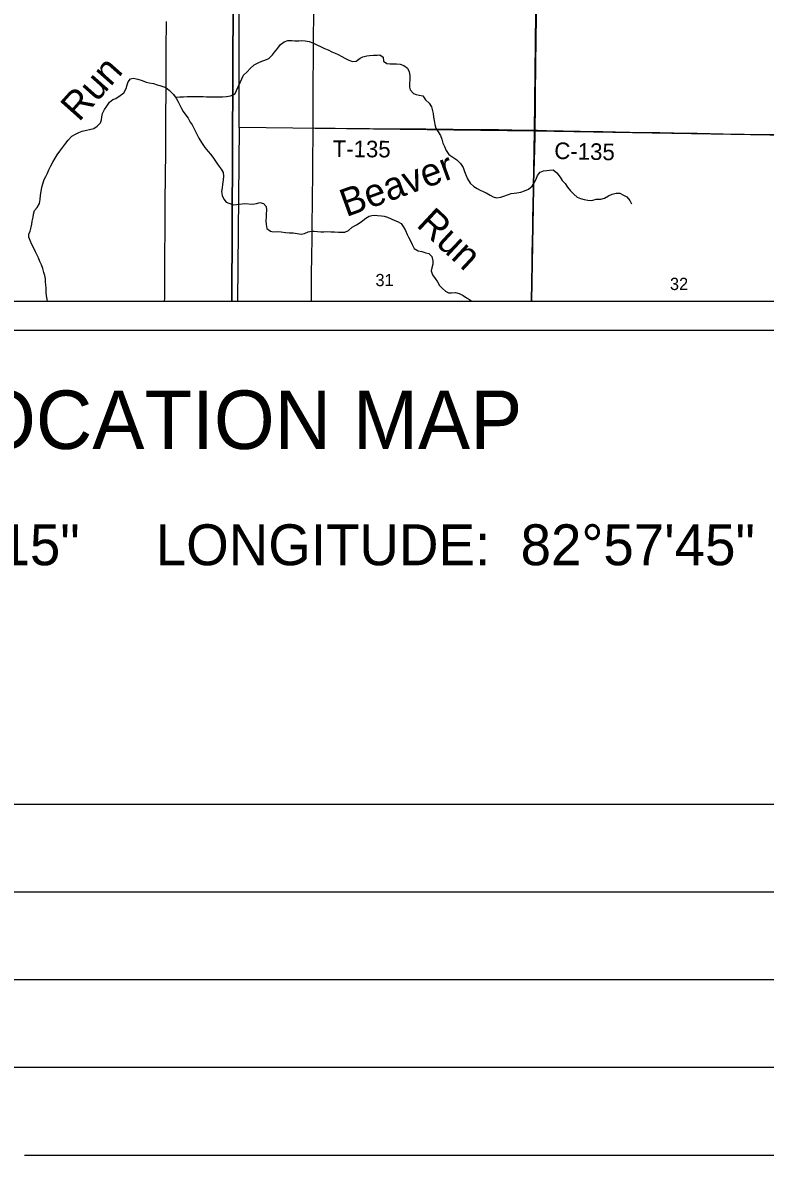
# Model space of a CAD drawing. Extents: x 0 to 45.9, y 0 to 22.
# Drawn here: x 4.739 to 7.28, y 11.177 to 15.053 of the extents above; entities that cross this region are included whole.
import ezdxf

# ---------------------------------------------------------------- set-up
doc = ezdxf.new("R2010")
doc.units = 0
for name, color, linetype in [('Default', 7, 'Continuous'), ('GM_X_County_Road', 7, 'Continuous'), ('GM_X_County_Road_Text', 7, 'Continuous'), ('GM_X_Minor_River', 7, 'Continuous'), ('GM_X_Minor_River_Text', 7, 'Continuous'), ('GM_X_Section', 7, 'Continuous'), ('GM_X_Section_Text', 7, 'Continuous'), ('GM_X_State_Route', 7, 'Continuous'), ('GM_X_Township_Road', 7, 'Continuous'), ('GM_X_Township_Road_Text', 7, 'Continuous'), ('SH_Border', 7, 'Continuous'), ('SH_Cut_Line', 7, 'Continuous'), ('SH_Text', 7, 'Continuous')]:
    doc.layers.add(name, color=color, linetype=linetype)

msp = doc.modelspace()

# ---------------------------------------------------------------- linework, layer by layer
at = {"layer": 'Default'}
msp.add_lwpolyline([(5.4606, 15.6588), (5.4538, 14.1), (8.9, 14.1), (8.9, 19.7611)], dxfattribs=at)
for points in [[(2.1, 19.7114), (2.1, 14.1), (5.4538, 14.1), (5.4606, 15.6588), (5.4651, 16.7018), (5.4694, 17.7061), (5.4802, 18.3214), (5.4737, 18.7216), (5.4752, 19.0482), (5.4759, 19.2109), (5.4773, 19.7108), (5.0826, 19.712), (3.7367, 19.7072), (2.15, 19.7113)], [(5.4738, 14.1), (6.4798, 14.1), (6.4893, 14.6816), (5.4789, 14.694)], [(6.4798, 14.1), (7.4874, 14.1), (7.4967, 14.6639), (6.4893, 14.6816)]]:
    msp.add_lwpolyline(points, close=True, dxfattribs=at)
at = {"layer": 'GM_X_County_Road'}
for points in [[(6.4922, 14.6848), (6.4925, 14.7031), (6.4931, 14.7497), (6.4935, 14.7963), (6.4943, 14.9175), (6.495, 14.9858), (6.496, 15.079), (6.4964, 15.1318), (6.497, 15.166), (6.4974, 15.1877), (6.4974, 15.225), (6.4976, 15.2871), (6.4982, 15.343), (6.4985, 15.3834), (6.4988, 15.4145), (6.499, 15.4642), (6.4995, 15.5077), (6.5001, 15.5667), (6.5003, 15.6009), (6.5006, 15.6413), (6.5009, 15.6926)], [(6.4795, 14.1), (6.4798, 14.11), (6.4802, 14.1348), (6.4804, 14.1721), (6.4812, 14.2156), (6.4819, 14.2653), (6.4835, 14.3429), (6.4842, 14.3833), (6.4852, 14.4268), (6.4865, 14.4733), (6.4877, 14.5137), (6.4896, 14.5789), (6.4919, 14.6628), (6.4922, 14.6848)], [(6.4922, 14.6848), (6.4995, 14.6846), (6.5306, 14.6838), (6.6454, 14.6815), (6.723, 14.6799), (6.7664, 14.6789), (6.8161, 14.678), (6.9185, 14.6762), (7.0116, 14.6744), (7.0457, 14.6739), (7.1357, 14.6725), (7.2071, 14.6713), (7.3157, 14.6695), (7.3933, 14.6683), (7.4585, 14.6672), (7.4866, 14.6668), (7.496, 14.6661)]]:
    msp.add_lwpolyline(points, dxfattribs=at)
at = {"layer": 'GM_X_Minor_River'}
for points in [[(5.4644, 14.8081), (5.4942, 14.8729), (5.5063, 14.8839), (5.5172, 14.8953), (5.5309, 14.9079), (5.5437, 14.9155), (5.557, 14.9205), (5.5668, 14.9239), (5.5812, 14.9304), (5.5933, 14.9422), (5.6001, 14.9517), (5.6111, 14.9654), (5.6209, 14.978), (5.633, 14.9871), (5.6455, 14.9917), (5.6592, 14.9914), (5.6698, 14.9907), (5.6831, 14.9907), (5.6933, 14.9915), (5.7054, 14.9908), (5.7183, 14.9882), (5.7316, 14.9833), (5.7446, 14.9772), (5.7571, 14.9712), (5.7708, 14.9644), (5.7841, 14.9596), (5.7959, 14.9528), (5.8073, 14.9483), (5.8175, 14.9434), (5.8304, 14.9362), (5.8407, 14.9309), (5.8548, 14.9241), (5.8669, 14.92), (5.8794, 14.9212), (5.8927, 14.9307), (5.9025, 14.9357), (5.9162, 14.9395), (5.9256, 14.9399), (5.9385, 14.9415), (5.951, 14.9415), (5.9609, 14.9423), (5.9716, 14.934), (5.9731, 14.9207), (5.9849, 14.9124), (5.9963, 14.9117), (6.0062, 14.9121), (6.0172, 14.9118), (6.0301, 14.9103), (6.043, 14.9058), (6.0552, 14.8964), (6.0609, 14.8839), (6.0632, 14.8714), (6.0633, 14.8573), (6.0618, 14.8459), (6.0615, 14.8319), (6.0638, 14.8224), (6.0752, 14.8107), (6.0851, 14.8066), (6.0949, 14.8047), (6.1075, 14.8017), (6.117, 14.7885), (6.1288, 14.7775), (6.1372, 14.7647), (6.1395, 14.7552), (6.143, 14.7412), (6.1445, 14.7287), (6.1461, 14.7173), (6.1488, 14.7044), (6.1519, 14.6911), (6.1606, 14.6786), (6.1686, 14.6665), (6.1725, 14.6544), (6.1756, 14.64), (6.1817, 14.6283), (6.1878, 14.615), (6.1969, 14.6014), (6.2103, 14.5927), (6.2239, 14.5829), (6.2365, 14.5704), (6.2453, 14.5568), (6.2499, 14.5435), (6.2549, 14.5314), (6.261, 14.5182), (6.2698, 14.5038), (6.2819, 14.4924), (6.2941, 14.4849), (6.304, 14.4792), (6.3146, 14.4747), (6.3249, 14.4706), (6.3382, 14.4623), (6.3481, 14.4566), (6.3598, 14.4529), (6.3746, 14.4552), (6.3849, 14.4587), (6.397, 14.4633), (6.4102, 14.4678), (6.4197, 14.4694), (6.4296, 14.4706), (6.4428, 14.4721), (6.4557, 14.4767), (6.4694, 14.4825)], [(4.8236, 14.1), (4.8223, 14.1059), (4.8202, 14.118), (4.8192, 14.1298), (4.8186, 14.1446), (4.818, 14.1541), (4.817, 14.1655), (4.8164, 14.1765), (4.8143, 14.1879), (4.8114, 14.1978), (4.807, 14.2115), (4.8026, 14.2237), (4.7975, 14.2348), (4.7923, 14.2478), (4.7872, 14.2592), (4.7824, 14.2688), (4.7757, 14.2829), (4.7702, 14.294), (4.7647, 14.307), (4.7599, 14.3188), (4.76, 14.3283), (4.764, 14.3392), (4.7676, 14.3524), (4.77, 14.3627), (4.7716, 14.3733), (4.7741, 14.3869), (4.7757, 14.3971), (4.7786, 14.4096), (4.7882, 14.4205), (4.796, 14.434), (4.7988, 14.4473), (4.8001, 14.4617), (4.8015, 14.4745), (4.8043, 14.4897), (4.8071, 14.5014), (4.8123, 14.5157), (4.8181, 14.5263), (4.8232, 14.5376), (4.8286, 14.5493), (4.8353, 14.5632), (4.8419, 14.5753), (4.8493, 14.5885), (4.8566, 14.6001), (4.8652, 14.6129), (4.8756, 14.6268), (4.886, 14.64), (4.8945, 14.6508), (4.9072, 14.6639), (4.9195, 14.6714), (4.9305, 14.6765), (4.9424, 14.6813), (4.9564, 14.6849), (4.9675, 14.687), (4.9816, 14.6903), (4.9934, 14.6988), (5.0046, 14.7097), (5.0078, 14.7203), (5.0098, 14.7301), (5.0122, 14.7418), (5.0189, 14.755), (5.0262, 14.7663), (5.0355, 14.781), (5.0474, 14.7895), (5.0569, 14.7936), (5.0719, 14.8029), (5.0842, 14.8129), (5.0927, 14.8276), (5.0963, 14.8397), (5.0998, 14.8503), (5.1076, 14.8601), (5.1171, 14.8622), (5.133, 14.859), (5.1473, 14.8542), (5.1609, 14.8495), (5.1715, 14.847), (5.1859, 14.8438), (5.1983, 14.8399), (5.2082, 14.8371), (5.218, 14.8339), (5.2278, 14.8304), (5.2395, 14.8215), (5.2541, 14.8069), (5.2641, 14.7938), (5.2689, 14.7843)], [(5.2613, 14.7974), (5.2657, 14.798), (5.2763, 14.799), (5.2885, 14.7988), (5.3018, 14.7994), (5.3132, 14.7996), (5.3238, 14.8002), (5.3557, 14.7998), (5.3674, 14.7993), (5.389, 14.799), (5.4027, 14.7984), (5.4129, 14.7983), (5.4224, 14.7985), (5.4357, 14.7995), (5.4494, 14.8023), (5.4644, 14.8081)], [(5.2689, 14.7843), (5.2823, 14.7591), (5.2882, 14.7484), (5.2971, 14.7361), (5.3046, 14.7261), (5.312, 14.7124), (5.3187, 14.7024), (5.3242, 14.6913), (5.3298, 14.6799), (5.3353, 14.6692), (5.3416, 14.657), (5.3501, 14.6428), (5.362, 14.6248), (5.3729, 14.6122), (5.3811, 14.6026), (5.3889, 14.5918), (5.3956, 14.5819), (5.403, 14.5719), (5.4109, 14.5608), (5.4176, 14.5512), (5.4242, 14.5401), (5.4256, 14.5272), (5.4243, 14.5147), (5.4218, 14.4992), (5.4209, 14.4871), (5.4192, 14.4749), (5.4213, 14.4613), (5.4264, 14.4487), (5.4343, 14.4387), (5.4441, 14.4344), (5.4603, 14.4297)], [(6.4694, 14.4825), (6.4815, 14.4931), (6.4882, 14.5045), (6.4958, 14.5171), (6.4999, 14.5292), (6.5086, 14.5414), (6.5203, 14.5456), (6.5317, 14.5468), (6.5412, 14.5483), (6.5537, 14.5484), (6.5659, 14.5389), (6.5773, 14.5238), (6.5842, 14.512), (6.5945, 14.5018), (6.6021, 14.4894), (6.6132, 14.4773), (6.6238, 14.4659), (6.6356, 14.455), (6.6474, 14.4512), (6.6599, 14.4474), (6.6717, 14.4452), (6.6861, 14.4437), (6.7009, 14.4483), (6.7161, 14.4488), (6.7289, 14.4515), (6.7433, 14.4595), (6.7554, 14.466), (6.7687, 14.4691), (6.782, 14.4691), (6.7945, 14.4627), (6.8055, 14.4567), (6.8158, 14.4442), (6.8216, 14.4321)], [(5.4603, 14.4297), (5.489, 14.4321), (5.4992, 14.4333), (5.525, 14.4319), (5.5383, 14.4334), (5.5504, 14.4373), (5.5625, 14.4343), (5.5721, 14.4233), (5.5729, 14.4104), (5.5722, 14.3979), (5.5718, 14.3884), (5.5707, 14.3744), (5.5715, 14.3622), (5.5742, 14.3482), (5.5864, 14.3388), (5.5959, 14.3369), (5.6103, 14.3385), (5.6228, 14.3366), (5.638, 14.334), (5.6513, 14.3333), (5.6638, 14.333), (5.6779, 14.3307), (5.6911, 14.3289), (5.7033, 14.3312), (5.7158, 14.3366), (5.7264, 14.3389), (5.7359, 14.3393), (5.7586, 14.3371), (5.7685, 14.3367), (5.7791, 14.3375), (5.7924, 14.3372), (5.8057, 14.3365), (5.8186, 14.3358), (5.8281, 14.3354), (5.8406, 14.3351), (5.8531, 14.3408), (5.8663, 14.3526), (5.8803, 14.3603), (5.8928, 14.3683), (5.9026, 14.3759), (5.9129, 14.3839), (5.9238, 14.39), (5.9333, 14.393), (5.9432, 14.3938), (5.9526, 14.3931), (5.9659, 14.3913), (5.9754, 14.3905), (5.9872, 14.3868), (5.9997, 14.3808), (6.0115, 14.3755), (6.021, 14.3717), (6.0335, 14.3657), (6.0404, 14.3555), (6.0484, 14.3411), (6.0538, 14.3282), (6.0591, 14.3184), (6.066, 14.3063), (6.0714, 14.2934), (6.0782, 14.2801), (6.0919, 14.2715), (6.1048, 14.2692), (6.1177, 14.2655), (6.128, 14.2621), (6.1383, 14.2526), (6.1417, 14.2379), (6.1414, 14.2257), (6.138, 14.2136), (6.1366, 14.203), (6.1408, 14.1897), (6.1499, 14.1768), (6.1583, 14.1655), (6.1652, 14.153), (6.1747, 14.1432), (6.1854, 14.1337), (6.1956, 14.1281), (6.2055, 14.1281), (6.2191, 14.1293), (6.2324, 14.1263), (6.2453, 14.1191), (6.2575, 14.1104), (6.2674, 14.1048), (6.2736, 14.1)]]:
    msp.add_lwpolyline(points, dxfattribs=at)
at = {"layer": 'GM_X_Section'}
for points in [[(6.5014, 15.6897), (6.4893, 14.6816), (5.4789, 14.694), (5.4804, 15.6984)], [(7.5224, 15.6742), (7.4967, 14.6639), (6.4893, 14.6816), (6.5014, 15.6897)]]:
    msp.add_lwpolyline(points, close=True, dxfattribs=at)
at = {"layer": 'GM_X_State_Route'}
msp.add_lwpolyline([(5.2243, 14.1), (5.2244, 14.1089), (5.2248, 14.1524), (5.2249, 14.1959), (5.2255, 14.2612), (5.2258, 14.3389), (5.2263, 14.3855), (5.2265, 14.4165), (5.2265, 14.4445), (5.2274, 14.5253), (5.228, 14.6123), (5.2284, 14.6806), (5.2289, 14.7552), (5.229, 14.7956), (5.2291, 14.8515), (5.2291, 14.9199), (5.2292, 14.9634), (5.2301, 15.0566)], dxfattribs=at)
at = {"layer": 'GM_X_Township_Road'}
for points in [[(5.7321, 14.6921), (5.7322, 14.7241), (5.7325, 14.8017), (5.7329, 14.8483), (5.7336, 14.9322), (5.7339, 14.9851), (5.7341, 15.0223), (5.7345, 15.0565), (5.7349, 15.1218), (5.7355, 15.1995), (5.7355, 15.2492), (5.7358, 15.3424), (5.736, 15.4014), (5.7362, 15.4449), (5.7365, 15.5444), (5.7368, 15.6314), (5.7367, 15.6624), (5.7368, 15.6752)], [(6.4922, 14.6848), (6.4925, 14.7031), (6.4931, 14.7497), (6.4935, 14.7963), (6.4943, 14.9175), (6.495, 14.9858), (6.496, 15.079), (6.4964, 15.1318), (6.497, 15.166), (6.4974, 15.1877), (6.4974, 15.225), (6.4976, 15.2871), (6.4982, 15.343), (6.4985, 15.3834), (6.4988, 15.4145), (6.499, 15.4642), (6.4995, 15.5077), (6.5001, 15.5667), (6.5003, 15.6009), (6.5006, 15.6413), (6.5009, 15.6926)], [(5.7262, 14.1), (5.7273, 14.1959), (5.7281, 14.2487), (5.7289, 14.317), (5.7292, 14.3698), (5.7298, 14.432), (5.7303, 14.4755), (5.7308, 14.5097), (5.7315, 14.5532), (5.7318, 14.5967), (5.732, 14.6557), (5.7321, 14.6921)], [(5.7321, 14.6921), (5.7393, 14.6919), (5.7455, 14.6917), (5.7734, 14.6916), (5.8075, 14.6913), (5.8572, 14.6907), (5.9254, 14.6901), (6.0744, 14.6892), (6.1178, 14.6887), (6.2109, 14.6876), (6.2543, 14.6871), (6.366, 14.6864), (6.4125, 14.6857), (6.4922, 14.6848)], [(6.4795, 14.1), (6.4798, 14.11), (6.4802, 14.1348), (6.4804, 14.1721), (6.4812, 14.2156), (6.4819, 14.2653), (6.4835, 14.3429), (6.4842, 14.3833), (6.4852, 14.4268), (6.4865, 14.4733), (6.4877, 14.5137), (6.4896, 14.5789), (6.4919, 14.6628), (6.4922, 14.6848)]]:
    msp.add_lwpolyline(points, dxfattribs=at)
at = {"layer": 'SH_Cut_Line'}
for p, q in [((2.1, 14.1), (8.9, 14.1)), ((2, 14), (9, 14)), ((7.7, 12.3767), (4.4937, 12.3767)), ((7.7, 12.0767), (3.9895, 12.0767)), ((7.7, 11.7767), (3.6192, 11.7767)), ((7.7, 11.4767), (3.3288, 11.4767)), ((7.7, 11.1767), (4.7452, 11.1767))]:
    msp.add_line(p, q, dxfattribs=at)
at = {"layer": 'SH_Text'}
for points in [[(2.1, 20.9), (2.1, 14.1), (5.4538, 14.1), (5.4606, 15.6588)], [(5.4606, 15.6588), (5.4538, 14.1), (8.9, 14.1), (8.9, 19.7611)]]:
    msp.add_lwpolyline(points, dxfattribs=at)

# ---------------------------------------------------------------- texts
at = {"layer": 'GM_X_County_Road_Text'}
msp.add_text('C-135', height=0.05682, rotation=358.6237, dxfattribs=at).set_placement((6.5569, 14.5863))
at = {"layer": 'GM_X_Minor_River_Text'}
for s, height, rotation, p in [('Run', 0.09471, 48.2995, (4.9311, 14.7107)), ('Beaver', 0.09471, 19.9764, (5.8453, 14.3867)), ('Run', 0.09472, 317.0785, (6.0821, 14.3575))]:
    msp.add_text(s, height=height, rotation=rotation, dxfattribs=at).set_placement(p)
at = {"layer": 'GM_X_Section_Text'}
for s, p in [('31', (5.9456, 14.1509)), ('32', (6.9531, 14.1376))]:
    msp.add_text(s, height=0.04186, rotation=0, dxfattribs=at).set_placement(p)
at = {"layer": 'GM_X_Township_Road_Text'}
msp.add_text('T-135', height=0.05682, rotation=359.4385, dxfattribs=at).set_placement((5.7988, 14.5931))
at = {"layer": 'SH_Border'}
for s, height, p in [('LOCATION MAP', 0.2, (4.4269, 13.5938)), ('LATITUDE:  40°37\'15"     LONGITUDE:  82°57\'45"', 0.14, (3.071, 13.1959))]:
    msp.add_text(s, height=height, dxfattribs=at).set_placement(p)

doc.saveas('drawing.dxf')
